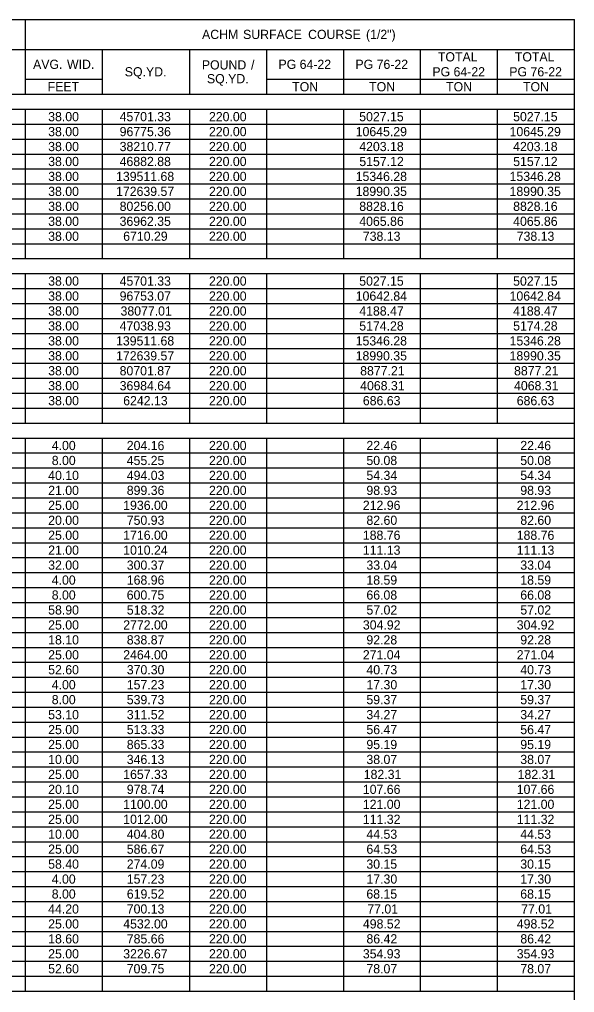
# Model space of a CAD drawing. Extents: x 2261867 to 2275370, y -3124789 to -3122260.
# Drawn here: x 2270145 to 2270507, y -3122908 to -3122274 of the extents above; entities that cross this region are included whole.
import ezdxf

# ---------------------------------------------------------------- set-up
doc = ezdxf.new("R2010")
doc.units = 0
doc.layers.add('Default', color=7, linetype='Continuous')

msp = doc.modelspace()

# ---------------------------------------------------------------- linework, layer by layer
at = {"layer": 'Default'}
for p, q in [((2269380.47, -3122273.85), (2270507.08, -3122273.85)), ((2270148.77, -3122322.6), (2270148.77, -3122273.85)), ((2270507.08, -3123434.1), (2270507.08, -3122273.85)), ((2270507.08, -3122322.6), (2270507.08, -3122273.85)), ((2269840.67, -3122293.35), (2270507.08, -3122293.35)), ((2270148.77, -3122293.35), (2270406.66, -3122293.35)), ((2270198.98, -3122322.6), (2270198.98, -3122293.35)), ((2270256.02, -3122322.6), (2270256.02, -3122293.35)), ((2270306.23, -3122322.6), (2270306.23, -3122293.35)), ((2270356.44, -3122322.6), (2270356.44, -3122293.35)), ((2270406.66, -3122322.6), (2270406.66, -3122293.35)), ((2270456.87, -3122322.6), (2270456.87, -3122293.35)), ((2270148.77, -3122312.85), (2270198.98, -3122312.85)), ((2270148.77, -3122322.6), (2270148.77, -3122312.85)), ((2270198.98, -3122322.6), (2270198.98, -3122312.85)), ((2270306.23, -3122312.85), (2270507.08, -3122312.85)), ((2269380.47, -3122322.6), (2270507.08, -3122322.6)), ((2270048.34, -3122322.6), (2270198.98, -3122322.6)), ((2270198.98, -3122322.6), (2270507.08, -3122322.6)), ((2269380.47, -3122332.35), (2270507.08, -3122332.35)), ((2270148.77, -3122429.85), (2270148.77, -3122332.35)), ((2270148.77, -3122429.85), (2270148.77, -3122332.35)), ((2270198.98, -3122429.85), (2270198.98, -3122332.35)), ((2270198.98, -3122429.85), (2270198.98, -3122332.35)), ((2270256.02, -3122429.85), (2270256.02, -3122332.35)), ((2270256.02, -3122429.85), (2270256.02, -3122332.35)), ((2270306.23, -3122429.85), (2270306.23, -3122332.35)), ((2270306.23, -3122429.85), (2270306.23, -3122332.35)), ((2270356.44, -3122429.85), (2270356.44, -3122332.35)), ((2270356.44, -3122429.85), (2270356.44, -3122332.35)), ((2270406.66, -3122429.85), (2270406.66, -3122332.35)), ((2270406.66, -3122429.85), (2270406.66, -3122332.35)), ((2270456.87, -3122429.85), (2270456.87, -3122332.35)), ((2270456.87, -3122429.85), (2270456.87, -3122332.35)), ((2270507.08, -3122429.85), (2270507.08, -3122332.35)), ((2269380.47, -3122342.1), (2270507.08, -3122342.1)), ((2269380.47, -3122351.85), (2270507.08, -3122351.85)), ((2269380.47, -3122361.6), (2270507.08, -3122361.6)), ((2269380.47, -3122371.35), (2270507.08, -3122371.35)), ((2269380.47, -3122381.1), (2270507.08, -3122381.1)), ((2269380.47, -3122390.85), (2270507.08, -3122390.85)), ((2269380.47, -3122400.6), (2270507.08, -3122400.6)), ((2269380.47, -3122410.35), (2270507.08, -3122410.35)), ((2269380.47, -3122420.1), (2270507.08, -3122420.1)), ((2269380.47, -3122429.85), (2270507.08, -3122429.85)), ((2269380.47, -3122429.85), (2270507.08, -3122429.85)), ((2269380.47, -3122439.6), (2270507.08, -3122439.6)), ((2270148.77, -3122537.1), (2270148.77, -3122439.6)), ((2270148.77, -3122537.1), (2270148.77, -3122439.6)), ((2270198.98, -3122537.1), (2270198.98, -3122439.6)), ((2270198.98, -3122537.1), (2270198.98, -3122439.6)), ((2270256.02, -3122537.1), (2270256.02, -3122439.6)), ((2270256.02, -3122537.1), (2270256.02, -3122439.6)), ((2270306.23, -3122537.1), (2270306.23, -3122439.6)), ((2270306.23, -3122537.1), (2270306.23, -3122439.6)), ((2270356.44, -3122537.1), (2270356.44, -3122439.6)), ((2270356.44, -3122537.1), (2270356.44, -3122439.6)), ((2270406.66, -3122537.1), (2270406.66, -3122439.6)), ((2270406.66, -3122537.1), (2270406.66, -3122439.6)), ((2270456.87, -3122537.1), (2270456.87, -3122439.6)), ((2270456.87, -3122537.1), (2270456.87, -3122439.6)), ((2270507.08, -3122537.1), (2270507.08, -3122439.6)), ((2269380.47, -3122449.35), (2270507.08, -3122449.35)), ((2269380.47, -3122459.1), (2270507.08, -3122459.1)), ((2269380.47, -3122468.85), (2270507.08, -3122468.85)), ((2269380.47, -3122478.6), (2270507.08, -3122478.6)), ((2269380.47, -3122488.35), (2270507.08, -3122488.35)), ((2269380.47, -3122498.1), (2270507.08, -3122498.1)), ((2269380.47, -3122507.85), (2270507.08, -3122507.85)), ((2269380.47, -3122517.6), (2270507.08, -3122517.6)), ((2269380.47, -3122527.35), (2270507.08, -3122527.35)), ((2269380.47, -3122537.1), (2270507.08, -3122537.1)), ((2269380.47, -3122537.1), (2270507.08, -3122537.1)), ((2269380.47, -3122546.85), (2270507.08, -3122546.85)), ((2270148.77, -3122907.6), (2270148.77, -3122546.85)), ((2270148.77, -3122907.6), (2270148.77, -3122546.85)), ((2270198.98, -3122907.6), (2270198.98, -3122546.85)), ((2270198.98, -3122907.6), (2270198.98, -3122546.85)), ((2270256.02, -3122907.6), (2270256.02, -3122546.85)), ((2270256.02, -3122907.6), (2270256.02, -3122546.85)), ((2270306.23, -3122907.6), (2270306.23, -3122546.85)), ((2270306.23, -3122907.6), (2270306.23, -3122546.85)), ((2270356.44, -3122907.6), (2270356.44, -3122546.85)), ((2270356.44, -3122907.6), (2270356.44, -3122546.85)), ((2270406.66, -3122907.6), (2270406.66, -3122546.85)), ((2270406.66, -3122907.6), (2270406.66, -3122546.85)), ((2270456.87, -3122907.6), (2270456.87, -3122546.85)), ((2270456.87, -3122907.6), (2270456.87, -3122546.85)), ((2270507.08, -3122907.6), (2270507.08, -3122546.85)), ((2269380.47, -3122556.6), (2270507.08, -3122556.6)), ((2269380.47, -3122566.35), (2270507.08, -3122566.35)), ((2269380.47, -3122576.1), (2270507.08, -3122576.1)), ((2269380.47, -3122585.85), (2270507.08, -3122585.85)), ((2269380.47, -3122595.6), (2270507.08, -3122595.6)), ((2269380.47, -3122605.35), (2270507.08, -3122605.35)), ((2269380.47, -3122615.1), (2270507.08, -3122615.1)), ((2269380.47, -3122624.85), (2270507.08, -3122624.85)), ((2269380.47, -3122634.6), (2270507.08, -3122634.6)), ((2269380.47, -3122644.35), (2270507.08, -3122644.35)), ((2269380.47, -3122654.1), (2270507.08, -3122654.1)), ((2269380.47, -3122663.85), (2270507.08, -3122663.85)), ((2269380.47, -3122673.6), (2270507.08, -3122673.6)), ((2269380.47, -3122683.35), (2270507.08, -3122683.35)), ((2269380.47, -3122693.1), (2270507.08, -3122693.1)), ((2269380.47, -3122702.85), (2270507.08, -3122702.85)), ((2269380.47, -3122712.6), (2270507.08, -3122712.6)), ((2269380.47, -3122722.35), (2270507.08, -3122722.35)), ((2269380.47, -3122732.1), (2270507.08, -3122732.1)), ((2269380.47, -3122741.85), (2270507.08, -3122741.85)), ((2269380.47, -3122751.6), (2270507.08, -3122751.6)), ((2269380.47, -3122761.35), (2270507.08, -3122761.35)), ((2269380.47, -3122771.1), (2270507.08, -3122771.1)), ((2269380.47, -3122780.85), (2270507.08, -3122780.85)), ((2269380.47, -3122790.6), (2270507.08, -3122790.6)), ((2269380.47, -3122800.35), (2270507.08, -3122800.35)), ((2269380.47, -3122810.1), (2270507.08, -3122810.1)), ((2269380.47, -3122819.85), (2270507.08, -3122819.85)), ((2269380.47, -3122829.6), (2270507.08, -3122829.6)), ((2269380.47, -3122839.35), (2270507.08, -3122839.35)), ((2269380.47, -3122849.1), (2270507.08, -3122849.1)), ((2269380.47, -3122858.85), (2270507.08, -3122858.85)), ((2269380.47, -3122868.6), (2270507.08, -3122868.6)), ((2269380.47, -3122878.35), (2270507.08, -3122878.35)), ((2269380.47, -3122888.1), (2270507.08, -3122888.1)), ((2269380.47, -3122897.85), (2270507.08, -3122897.85)), ((2269991.31, -3122897.85), (2270507.08, -3122897.85)), ((2269380.47, -3122907.6), (2270507.08, -3122907.6)), ((2269991.31, -3122907.6), (2270507.08, -3122907.6))]:
    msp.add_line(p, q, dxfattribs=at)

# ---------------------------------------------------------------- texts
for s, p in [('ACHM', (2270263.99, -3122286.6)), (' SURFACE', (2270288.54, -3122286.6)), (' COURSE', (2270330.98, -3122286.6)), (' (1/2")', (2270368.76, -3122286.6)), ('TOTAL', (2270417.92, -3122301.22)), ('TOTAL', (2270468.13, -3122301.22)), ('AVG.', (2270153.73, -3122306.1)), (' WID.', (2270173.65, -3122306.1)), ('POUND', (2270263.86, -3122306.47)), (' /', (2270293.72, -3122306.47)), ('PG', (2270313.87, -3122306.1)), (' 64-22', (2270325.47, -3122306.1)), ('PG', (2270364.08, -3122306.1)), (' 76-22', (2270375.69, -3122306.1)), ('SQ.YD.', (2270213.58, -3122310.97)), ('PG', (2270414.29, -3122310.97)), (' 64-22', (2270425.9, -3122310.97)), ('PG', (2270464.5, -3122310.97)), (' 76-22', (2270476.11, -3122310.97)), ('FEET', (2270163.25, -3122320.72)), ('SQ.YD.', (2270267.2, -3122315.47)), ('TON', (2270322.82, -3122320.72)), ('TON', (2270373.04, -3122320.72)), ('TON', (2270423.25, -3122320.72)), ('TON', (2270473.46, -3122320.72)), ('38.00', (2270163.59, -3122340.22)), ('45701.33', (2270210.22, -3122340.22)), ('220.00', (2270268.51, -3122340.22)), ('5027.15', (2270366.57, -3122340.22)), ('5027.15', (2270467, -3122340.22)), ('38.00', (2270163.59, -3122349.97)), ('96775.36', (2270210.22, -3122349.97)), ('220.00', (2270268.51, -3122349.97)), ('10645.29', (2270364.26, -3122349.97)), ('10645.29', (2270464.69, -3122349.97)), ('38.00', (2270163.59, -3122359.72)), ('38210.77', (2270210.22, -3122359.72)), ('220.00', (2270268.51, -3122359.72)), ('4203.18', (2270366.59, -3122359.72)), ('4203.18', (2270467.02, -3122359.72)), ('38.00', (2270163.59, -3122369.47)), ('46882.88', (2270210.21, -3122369.47)), ('220.00', (2270268.51, -3122369.47)), ('5157.12', (2270366.63, -3122369.47)), ('5157.12', (2270467.05, -3122369.47)), ('38.00', (2270163.59, -3122379.22)), ('139511.68', (2270207.88, -3122379.22)), ('220.00', (2270268.51, -3122379.22)), ('15346.28', (2270364.26, -3122379.22)), ('15346.28', (2270464.69, -3122379.22)), ('38.00', (2270163.59, -3122388.97)), ('172639.57', (2270207.89, -3122388.97)), ('220.00', (2270268.51, -3122388.97)), ('18990.35', (2270364.24, -3122388.97)), ('18990.35', (2270464.67, -3122388.97)), ('38.00', (2270163.59, -3122398.72)), ('80256.00', (2270210.23, -3122398.72)), ('220.00', (2270268.51, -3122398.72)), ('8828.16', (2270366.6, -3122398.72)), ('8828.16', (2270467.02, -3122398.72)), ('38.00', (2270163.59, -3122408.47)), ('36962.35', (2270210.19, -3122408.47)), ('220.00', (2270268.51, -3122408.47)), ('4065.86', (2270366.6, -3122408.47)), ('4065.86', (2270467.02, -3122408.47)), ('38.00', (2270163.59, -3122418.22)), ('6710.29', (2270212.54, -3122418.22)), ('220.00', (2270268.51, -3122418.22)), ('738.13', (2270368.93, -3122418.22)), ('738.13', (2270469.35, -3122418.22)), ('38.00', (2270163.59, -3122447.47)), ('45701.33', (2270210.22, -3122447.47)), ('220.00', (2270268.51, -3122447.47)), ('5027.15', (2270366.57, -3122447.47)), ('5027.15', (2270467, -3122447.47)), ('38.00', (2270163.59, -3122457.22)), ('96753.07', (2270210.22, -3122457.22)), ('220.00', (2270268.51, -3122457.22)), ('10642.84', (2270364.28, -3122457.22)), ('10642.84', (2270464.7, -3122457.22)), ('38.00', (2270163.59, -3122466.97)), ('38077.01', (2270210.8, -3122466.97)), ('220.00', (2270268.51, -3122466.97)), ('4188.47', (2270366.6, -3122466.97)), ('4188.47', (2270467.02, -3122466.97)), ('38.00', (2270163.59, -3122476.72)), ('47038.93', (2270210.22, -3122476.72)), ('220.00', (2270268.51, -3122476.72)), ('5174.28', (2270366.59, -3122476.72)), ('5174.28', (2270467.02, -3122476.72)), ('38.00', (2270163.59, -3122486.47)), ('139511.68', (2270207.88, -3122486.47)), ('220.00', (2270268.51, -3122486.47)), ('15346.28', (2270364.26, -3122486.47)), ('15346.28', (2270464.69, -3122486.47)), ('38.00', (2270163.59, -3122496.22)), ('172639.57', (2270207.89, -3122496.22)), ('220.00', (2270268.51, -3122496.22)), ('18990.35', (2270364.24, -3122496.22)), ('18990.35', (2270464.67, -3122496.22)), ('38.00', (2270163.59, -3122505.97)), ('80701.87', (2270210.22, -3122505.97)), ('220.00', (2270268.51, -3122505.97)), ('8877.21', (2270367.18, -3122505.97)), ('8877.21', (2270467.6, -3122505.97)), ('38.00', (2270163.59, -3122515.72)), ('36984.64', (2270210.23, -3122515.72)), ('220.00', (2270268.51, -3122515.72)), ('4068.31', (2270367.18, -3122515.72)), ('4068.31', (2270467.6, -3122515.72)), ('38.00', (2270163.59, -3122525.47)), ('6242.13', (2270212.55, -3122525.47)), ('220.00', (2270268.51, -3122525.47)), ('686.63', (2270368.93, -3122525.47)), ('686.63', (2270469.35, -3122525.47)), ('4.00', (2270165.92, -3122554.72)), ('204.16', (2270214.88, -3122554.72)), ('220.00', (2270268.51, -3122554.72)), ('22.46', (2270371.26, -3122554.72)), ('22.46', (2270471.68, -3122554.72)), ('8.00', (2270165.92, -3122564.47)), ('455.25', (2270214.85, -3122564.47)), ('220.00', (2270268.51, -3122564.47)), ('50.08', (2270371.25, -3122564.47)), ('50.08', (2270471.68, -3122564.47)), ('40.10', (2270163.59, -3122574.22)), ('494.03', (2270214.88, -3122574.22)), ('220.00', (2270268.51, -3122574.22)), ('54.34', (2270371.27, -3122574.22)), ('54.34', (2270471.69, -3122574.22)), ('21.00', (2270163.59, -3122583.97)), ('899.36', (2270214.88, -3122583.97)), ('220.00', (2270268.51, -3122583.97)), ('98.93', (2270371.26, -3122583.97)), ('98.93', (2270471.68, -3122583.97)), ('25.00', (2270163.59, -3122593.72)), ('1936.00', (2270212.56, -3122593.72)), ('220.00', (2270268.51, -3122593.72)), ('212.96', (2270368.93, -3122593.72)), ('212.96', (2270469.35, -3122593.72)), ('20.00', (2270163.59, -3122603.47)), ('750.93', (2270214.88, -3122603.47)), ('220.00', (2270268.51, -3122603.47)), ('82.60', (2270371.27, -3122603.47)), ('82.60', (2270471.69, -3122603.47)), ('25.00', (2270163.59, -3122613.22)), ('1716.00', (2270212.56, -3122613.22)), ('220.00', (2270268.51, -3122613.22)), ('188.76', (2270368.93, -3122613.22)), ('188.76', (2270469.35, -3122613.22)), ('21.00', (2270163.59, -3122622.97)), ('1010.24', (2270212.56, -3122622.97)), ('220.00', (2270268.51, -3122622.97)), ('111.13', (2270368.93, -3122622.97)), ('111.13', (2270469.35, -3122622.97)), ('32.00', (2270163.59, -3122632.72)), ('300.37', (2270214.88, -3122632.72)), ('220.00', (2270268.51, -3122632.72)), ('33.04', (2270371.27, -3122632.72)), ('33.04', (2270471.69, -3122632.72)), ('4.00', (2270165.92, -3122642.47)), ('168.96', (2270214.88, -3122642.47)), ('220.00', (2270268.51, -3122642.47)), ('18.59', (2270371.25, -3122642.47)), ('18.59', (2270471.68, -3122642.47)), ('8.00', (2270165.92, -3122652.22)), ('600.75', (2270214.85, -3122652.22)), ('220.00', (2270268.51, -3122652.22)), ('66.08', (2270371.25, -3122652.22)), ('66.08', (2270471.68, -3122652.22)), ('58.90', (2270163.59, -3122661.97)), ('518.32', (2270214.91, -3122661.97)), ('220.00', (2270268.51, -3122661.97)), ('57.02', (2270371.29, -3122661.97)), ('57.02', (2270471.71, -3122661.97)), ('25.00', (2270163.59, -3122671.72)), ('2772.00', (2270212.56, -3122671.72)), ('220.00', (2270268.51, -3122671.72)), ('304.92', (2270368.96, -3122671.72)), ('304.92', (2270469.38, -3122671.72)), ('18.10', (2270163.59, -3122681.47)), ('838.87', (2270214.88, -3122681.47)), ('220.00', (2270268.51, -3122681.47)), ('92.28', (2270371.25, -3122681.47)), ('92.28', (2270471.68, -3122681.47)), ('25.00', (2270163.59, -3122691.22)), ('2464.00', (2270212.56, -3122691.22)), ('220.00', (2270268.51, -3122691.22)), ('271.04', (2270368.94, -3122691.22)), ('271.04', (2270469.36, -3122691.22)), ('52.60', (2270163.59, -3122700.97)), ('370.30', (2270214.89, -3122700.97)), ('220.00', (2270268.51, -3122700.97)), ('40.73', (2270371.26, -3122700.97)), ('40.73', (2270471.68, -3122700.97)), ('4.00', (2270165.92, -3122710.72)), ('157.23', (2270214.88, -3122710.72)), ('220.00', (2270268.51, -3122710.72)), ('17.30', (2270371.27, -3122710.72)), ('17.30', (2270471.69, -3122710.72)), ('8.00', (2270165.92, -3122720.47)), ('539.73', (2270214.88, -3122720.47)), ('220.00', (2270268.51, -3122720.47)), ('59.37', (2270371.26, -3122720.47)), ('59.37', (2270471.68, -3122720.47)), ('53.10', (2270163.59, -3122730.22)), ('311.52', (2270214.91, -3122730.22)), ('220.00', (2270268.51, -3122730.22)), ('34.27', (2270371.26, -3122730.22)), ('34.27', (2270471.68, -3122730.22)), ('25.00', (2270163.59, -3122739.97)), ('513.33', (2270214.88, -3122739.97)), ('220.00', (2270268.51, -3122739.97)), ('56.47', (2270371.26, -3122739.97)), ('56.47', (2270471.68, -3122739.97)), ('25.00', (2270163.59, -3122749.72)), ('865.33', (2270214.88, -3122749.72)), ('220.00', (2270268.51, -3122749.72)), ('95.19', (2270371.25, -3122749.72)), ('95.19', (2270471.68, -3122749.72)), ('10.00', (2270163.59, -3122759.47)), ('346.13', (2270214.88, -3122759.47)), ('220.00', (2270268.51, -3122759.47)), ('38.07', (2270371.26, -3122759.47)), ('38.07', (2270471.68, -3122759.47)), ('25.00', (2270163.59, -3122769.22)), ('1657.33', (2270212.55, -3122769.22)), ('220.00', (2270268.51, -3122769.22)), ('182.31', (2270369.51, -3122769.22)), ('182.31', (2270469.93, -3122769.22)), ('20.10', (2270163.59, -3122778.97)), ('978.74', (2270214.89, -3122778.97)), ('220.00', (2270268.51, -3122778.97)), ('107.66', (2270368.93, -3122778.97)), ('107.66', (2270469.35, -3122778.97)), ('25.00', (2270163.59, -3122788.72)), ('1100.00', (2270212.56, -3122788.72)), ('220.00', (2270268.51, -3122788.72)), ('121.00', (2270368.94, -3122788.72)), ('121.00', (2270469.36, -3122788.72)), ('25.00', (2270163.59, -3122798.47)), ('1012.00', (2270212.56, -3122798.47)), ('220.00', (2270268.51, -3122798.47)), ('111.32', (2270368.96, -3122798.47)), ('111.32', (2270469.38, -3122798.47)), ('10.00', (2270163.59, -3122808.22)), ('404.80', (2270214.89, -3122808.22)), ('220.00', (2270268.51, -3122808.22)), ('44.53', (2270371.26, -3122808.22)), ('44.53', (2270471.68, -3122808.22)), ('25.00', (2270163.59, -3122817.97)), ('586.67', (2270214.88, -3122817.97)), ('220.00', (2270268.51, -3122817.97)), ('64.53', (2270371.26, -3122817.97)), ('64.53', (2270471.68, -3122817.97)), ('58.40', (2270163.59, -3122827.72)), ('274.09', (2270214.87, -3122827.72)), ('220.00', (2270268.51, -3122827.72)), ('30.15', (2270371.23, -3122827.72)), ('30.15', (2270471.66, -3122827.72)), ('4.00', (2270165.92, -3122837.47)), ('157.23', (2270214.88, -3122837.47)), ('220.00', (2270268.51, -3122837.47)), ('17.30', (2270371.27, -3122837.47)), ('17.30', (2270471.69, -3122837.47)), ('8.00', (2270165.92, -3122847.22)), ('619.52', (2270214.91, -3122847.22)), ('220.00', (2270268.51, -3122847.22)), ('68.15', (2270371.23, -3122847.22)), ('68.15', (2270471.66, -3122847.22)), ('44.20', (2270163.59, -3122856.97)), ('700.13', (2270214.88, -3122856.97)), ('220.00', (2270268.51, -3122856.97)), ('77.01', (2270371.84, -3122856.97)), ('77.01', (2270472.26, -3122856.97)), ('25.00', (2270163.59, -3122866.72)), ('4532.00', (2270212.56, -3122866.72)), ('220.00', (2270268.51, -3122866.72)), ('498.52', (2270368.96, -3122866.72)), ('498.52', (2270469.38, -3122866.72)), ('18.60', (2270163.59, -3122876.47)), ('785.66', (2270214.88, -3122876.47)), ('220.00', (2270268.51, -3122876.47)), ('86.42', (2270371.29, -3122876.47)), ('86.42', (2270471.71, -3122876.47)), ('25.00', (2270163.59, -3122886.22)), ('3226.67', (2270212.55, -3122886.22)), ('220.00', (2270268.51, -3122886.22)), ('354.93', (2270368.93, -3122886.22)), ('354.93', (2270469.35, -3122886.22)), ('52.60', (2270163.59, -3122895.97)), ('709.75', (2270214.85, -3122895.97)), ('220.00', (2270268.51, -3122895.97)), ('78.07', (2270371.26, -3122895.97)), ('78.07', (2270471.68, -3122895.97))]:
    msp.add_text(s, height=6, dxfattribs=at).set_placement(p)

doc.saveas('drawing.dxf')
